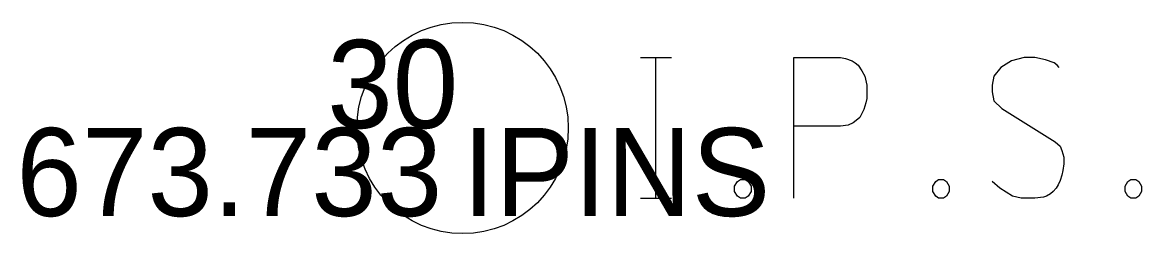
# Model space of a CAD drawing. Extents: x 2197382 to 2204062, y 634117 to 636522.
# Drawn here: x 2203453.82 to 2203466.52, y 635834.87 to 635837.27 of the extents above; entities that cross this region are included whole.
import ezdxf

# ---------------------------------------------------------------- set-up
doc = ezdxf.new("R2010")
doc.units = 0
for name, color, linetype in [('SC_Scratch1', 7, 'Continuous'), ('SH_Border', 7, 'Continuous'), ('SH_Cut_Line', 7, 'Continuous'), ('SH_Data', 7, 'Continuous')]:
    doc.layers.add(name, color=color, linetype=linetype)

msp = doc.modelspace()

# ---------------------------------------------------------------- linework, layer by layer
at = {"layer": 'SC_Scratch1'}
for points in [[(2203460.834, 635836.869), (2203461.187, 635836.869)], [(2203460.834, 635836.869), (2203461.187, 635836.869)], [(2203460.834, 635836.869), (2203461.187, 635836.869)], [(2203461.01, 635835.269), (2203461.01, 635836.869)], [(2203461.01, 635835.269), (2203461.01, 635836.869)], [(2203461.01, 635835.269), (2203461.01, 635836.869)], [(2203462.576, 635835.269), (2203462.576, 635836.869), (2203463.105, 635836.869), (2203463.16, 635836.856), (2203463.237, 635836.831), (2203463.27, 635836.806), (2203463.303, 635836.78), (2203463.347, 635836.717), (2203463.38, 635836.654), (2203463.402, 635836.554), (2203463.402, 635836.402), (2203463.391, 635836.352), (2203463.369, 635836.276), (2203463.325, 635836.188), (2203463.281, 635836.151), (2203463.248, 635836.125), (2203463.193, 635836.1), (2203463.105, 635836.088), (2203462.576, 635836.088)], [(2203462.576, 635835.269), (2203462.576, 635836.869), (2203463.105, 635836.869), (2203463.16, 635836.856), (2203463.237, 635836.831), (2203463.27, 635836.806), (2203463.303, 635836.78), (2203463.347, 635836.717), (2203463.38, 635836.654), (2203463.402, 635836.554), (2203463.402, 635836.402), (2203463.391, 635836.352), (2203463.369, 635836.276), (2203463.325, 635836.188), (2203463.281, 635836.151), (2203463.248, 635836.125), (2203463.193, 635836.1), (2203463.105, 635836.088), (2203462.576, 635836.088)], [(2203462.576, 635835.269), (2203462.576, 635836.869), (2203463.105, 635836.869), (2203463.16, 635836.856), (2203463.237, 635836.831), (2203463.27, 635836.806), (2203463.303, 635836.78), (2203463.347, 635836.717), (2203463.38, 635836.654), (2203463.402, 635836.554), (2203463.402, 635836.402), (2203463.391, 635836.352), (2203463.369, 635836.276), (2203463.325, 635836.188), (2203463.281, 635836.151), (2203463.248, 635836.125), (2203463.193, 635836.1), (2203463.105, 635836.088), (2203462.576, 635836.088)], [(2203465.585, 635836.755), (2203465.563, 635836.78), (2203465.53, 635836.806), (2203465.431, 635836.843), (2203465.309, 635836.869), (2203465.221, 635836.869), (2203465.188, 635836.869), (2203465.045, 635836.831), (2203464.924, 635836.755), (2203464.846, 635836.654), (2203464.824, 635836.554), (2203464.824, 635836.478), (2203464.846, 635836.377), (2203464.935, 635836.289), (2203465.541, 635835.911), (2203465.596, 635835.861), (2203465.618, 635835.81), (2203465.64, 635835.735), (2203465.64, 635835.659), (2203465.629, 635835.584), (2203465.618, 635835.533), (2203465.596, 635835.47), (2203465.574, 635835.42), (2203465.552, 635835.382), (2203465.519, 635835.344), (2203465.486, 635835.319), (2203465.442, 635835.294), (2203465.409, 635835.281), (2203465.309, 635835.269), (2203465.155, 635835.269), (2203465.056, 635835.294), (2203464.912, 635835.382), (2203464.824, 635835.458)], [(2203465.585, 635836.755), (2203465.563, 635836.78), (2203465.53, 635836.806), (2203465.431, 635836.843), (2203465.309, 635836.869), (2203465.221, 635836.869), (2203465.188, 635836.869), (2203465.045, 635836.831), (2203464.924, 635836.755), (2203464.846, 635836.654), (2203464.824, 635836.554), (2203464.824, 635836.478), (2203464.846, 635836.377), (2203464.935, 635836.289), (2203465.541, 635835.911), (2203465.596, 635835.861), (2203465.618, 635835.81), (2203465.64, 635835.735), (2203465.64, 635835.659), (2203465.629, 635835.584), (2203465.618, 635835.533), (2203465.596, 635835.47), (2203465.574, 635835.42), (2203465.552, 635835.382), (2203465.519, 635835.344), (2203465.486, 635835.319), (2203465.442, 635835.294), (2203465.409, 635835.281), (2203465.309, 635835.269), (2203465.155, 635835.269), (2203465.056, 635835.294), (2203464.912, 635835.382), (2203464.824, 635835.458)], [(2203465.585, 635836.755), (2203465.563, 635836.78), (2203465.53, 635836.806), (2203465.431, 635836.843), (2203465.309, 635836.869), (2203465.221, 635836.869), (2203465.188, 635836.869), (2203465.045, 635836.831), (2203464.924, 635836.755), (2203464.846, 635836.654), (2203464.824, 635836.554), (2203464.824, 635836.478), (2203464.846, 635836.377), (2203464.935, 635836.289), (2203465.541, 635835.911), (2203465.596, 635835.861), (2203465.618, 635835.81), (2203465.64, 635835.735), (2203465.64, 635835.659), (2203465.629, 635835.584), (2203465.618, 635835.533), (2203465.596, 635835.47), (2203465.574, 635835.42), (2203465.552, 635835.382), (2203465.519, 635835.344), (2203465.486, 635835.319), (2203465.442, 635835.294), (2203465.409, 635835.281), (2203465.309, 635835.269), (2203465.155, 635835.269), (2203465.056, 635835.294), (2203464.912, 635835.382), (2203464.824, 635835.458)], [(2203461.969, 635835.483), (2203462.024, 635835.483), (2203462.058, 635835.458), (2203462.091, 635835.407), (2203462.091, 635835.344), (2203462.058, 635835.294), (2203462.024, 635835.269), (2203461.969, 635835.269), (2203461.936, 635835.294), (2203461.903, 635835.344), (2203461.903, 635835.407), (2203461.936, 635835.458), (2203461.969, 635835.483)], [(2203461.969, 635835.483), (2203462.024, 635835.483), (2203462.058, 635835.458), (2203462.091, 635835.407), (2203462.091, 635835.344), (2203462.058, 635835.294), (2203462.024, 635835.269), (2203461.969, 635835.269), (2203461.936, 635835.294), (2203461.903, 635835.344), (2203461.903, 635835.407), (2203461.936, 635835.458), (2203461.969, 635835.483)], [(2203461.969, 635835.483), (2203462.024, 635835.483), (2203462.058, 635835.458), (2203462.091, 635835.407), (2203462.091, 635835.344), (2203462.058, 635835.294), (2203462.024, 635835.269), (2203461.969, 635835.269), (2203461.936, 635835.294), (2203461.903, 635835.344), (2203461.903, 635835.407), (2203461.936, 635835.458), (2203461.969, 635835.483)], [(2203464.218, 635835.483), (2203464.273, 635835.483), (2203464.306, 635835.458), (2203464.339, 635835.407), (2203464.339, 635835.344), (2203464.306, 635835.294), (2203464.273, 635835.269), (2203464.218, 635835.269), (2203464.185, 635835.294), (2203464.152, 635835.344), (2203464.152, 635835.407), (2203464.185, 635835.458), (2203464.218, 635835.483)], [(2203464.218, 635835.483), (2203464.273, 635835.483), (2203464.306, 635835.458), (2203464.339, 635835.407), (2203464.339, 635835.344), (2203464.306, 635835.294), (2203464.273, 635835.269), (2203464.218, 635835.269), (2203464.185, 635835.294), (2203464.152, 635835.344), (2203464.152, 635835.407), (2203464.185, 635835.458), (2203464.218, 635835.483)], [(2203464.218, 635835.483), (2203464.273, 635835.483), (2203464.306, 635835.458), (2203464.339, 635835.407), (2203464.339, 635835.344), (2203464.306, 635835.294), (2203464.273, 635835.269), (2203464.218, 635835.269), (2203464.185, 635835.294), (2203464.152, 635835.344), (2203464.152, 635835.407), (2203464.185, 635835.458), (2203464.218, 635835.483)], [(2203466.401, 635835.483), (2203466.456, 635835.483), (2203466.489, 635835.458), (2203466.522, 635835.407), (2203466.522, 635835.344), (2203466.489, 635835.294), (2203466.456, 635835.269), (2203466.401, 635835.269), (2203466.367, 635835.294), (2203466.335, 635835.344), (2203466.335, 635835.407), (2203466.367, 635835.458), (2203466.401, 635835.483)], [(2203466.401, 635835.483), (2203466.456, 635835.483), (2203466.489, 635835.458), (2203466.522, 635835.407), (2203466.522, 635835.344), (2203466.489, 635835.294), (2203466.456, 635835.269), (2203466.401, 635835.269), (2203466.367, 635835.294), (2203466.335, 635835.344), (2203466.335, 635835.407), (2203466.367, 635835.458), (2203466.401, 635835.483)], [(2203466.401, 635835.483), (2203466.456, 635835.483), (2203466.489, 635835.458), (2203466.522, 635835.407), (2203466.522, 635835.344), (2203466.489, 635835.294), (2203466.456, 635835.269), (2203466.401, 635835.269), (2203466.367, 635835.294), (2203466.335, 635835.344), (2203466.335, 635835.407), (2203466.367, 635835.458), (2203466.401, 635835.483)], [(2203460.834, 635835.269), (2203461.187, 635835.269)], [(2203460.834, 635835.269), (2203461.187, 635835.269)], [(2203460.834, 635835.269), (2203461.187, 635835.269)]]:
    msp.add_lwpolyline(points, dxfattribs=at)
msp.add_circle((2203458.815, 635836.067), 1.2, dxfattribs=at)
msp.add_circle((2203458.815, 635836.067), 1.2, dxfattribs=at)
msp.add_circle((2203458.815, 635836.067), 1.2, dxfattribs=at)

# ---------------------------------------------------------------- texts
at = {"layer": 'SH_Border'}
msp.add_text('IPINS', height=1, dxfattribs=at).set_placement((2203458.815, 635835.067))
msp.add_text('IPINS', height=1, dxfattribs=at).set_placement((2203458.815, 635835.067))
msp.add_text('IPINS', height=1, dxfattribs=at).set_placement((2203458.815, 635835.067))
at = {"layer": 'SH_Cut_Line'}
msp.add_text('30', height=1, dxfattribs=at).set_placement((2203457.279, 635836.067))
msp.add_text('30', height=1, dxfattribs=at).set_placement((2203457.279, 635836.067))
msp.add_text('30', height=1, dxfattribs=at).set_placement((2203457.279, 635836.067))
at = {"layer": 'SH_Data'}
msp.add_text('673.733', height=1, dxfattribs=at).set_placement((2203453.751, 635835.067))
msp.add_text('673.733', height=1, dxfattribs=at).set_placement((2203453.751, 635835.067))
msp.add_text('673.733', height=1, dxfattribs=at).set_placement((2203453.751, 635835.067))

doc.saveas('drawing.dxf')
